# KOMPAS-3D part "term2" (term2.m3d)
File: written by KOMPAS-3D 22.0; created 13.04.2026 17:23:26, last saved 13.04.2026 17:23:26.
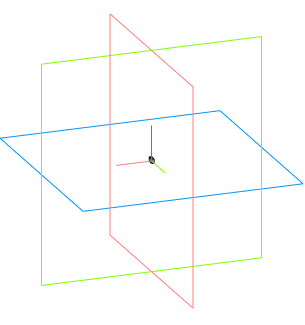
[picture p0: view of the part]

Document properties: Автор: Andrey; Полное имя файла: C:\Users\User1\Documents\term2.m3d

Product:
- Part/product: term2

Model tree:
1. Операция без истории:1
